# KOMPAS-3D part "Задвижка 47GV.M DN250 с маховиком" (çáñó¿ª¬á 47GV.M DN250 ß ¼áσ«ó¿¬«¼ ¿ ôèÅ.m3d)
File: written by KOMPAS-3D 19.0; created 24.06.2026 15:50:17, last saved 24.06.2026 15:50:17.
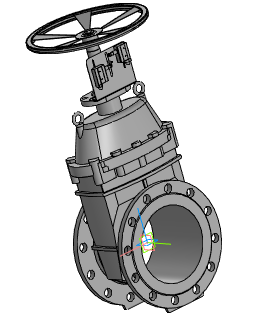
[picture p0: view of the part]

Document properties: Автор: Евгений; Полное имя файла: Z:\3.Личные\sachek\Dendor\3D для проектировщиков\2.7 Тип 47GV.M Задвижка клиновая фланцевая с обрезиненным клином\47GV.M DN250\Задвижка 47GV.M DN250 с маховиком.a3d

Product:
- Part/product: Задвижка 47GV.M DN250 с маховиком
    Масса: 161.472
    source file: ..\47GV.M DN250\DR.47GVM.250.16.00.00 - Задвижка с обрезиненным клином DN250.spw
  - Component: Задвижка с обрезиненным клином DN250. Сборочный чертеж  | designation DR.47GVM.250.16.00.00СБ  | pos. 0  | Масса: 79.6129; Раздел спецификации: Документация; Форматы листов документа: 2xA3; source file: ..\47GV.M DN250\DR.47GVM.250.16.00.000 СБ - Задвижка с обрезиненным клином DN250.cdw

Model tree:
1. Операция без истории:1

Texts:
  Точка начала. Х
  Точка начала. Y
  Точка начала. Z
